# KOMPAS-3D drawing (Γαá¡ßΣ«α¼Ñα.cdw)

Referenced files in C:\Documents and Settings\501\Рабочий стол\: кровать.jpg, комод.jpg, 2010-11-17_163100.png, 2010-11-17_163129.png
Referenced files: трансформер.cdw
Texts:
  кровать трансформер
  кровать взрослая
  кровать взрослая изголовье
  кровать детская
  комод-пелинальница
  планка деревянная
  кровать трансформер-
Dimensions and other numbers on the sheet: 800; 950; 892; 1932; 600; 592; 50; 150; 80; 200; 10; 1900; 942; 30; 292; 365; 100; 60; 426; 595; 658; 52; 43; 40; 70; 113; 213; 313; 413; 513; 143; 160; 170; 173; 112; 212; 312; 412; 512; 73; 598; 15; 45; 125; 205; 285; 4; 1:1; 1; 11; 2; 3; 5; 6; 7; 8; 9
